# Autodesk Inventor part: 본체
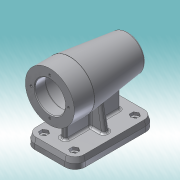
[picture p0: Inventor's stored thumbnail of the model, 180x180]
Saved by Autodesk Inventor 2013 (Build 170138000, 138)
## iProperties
Created: 2017-01
Part Number: 본체
Material: 알루미늄 6061
Document SubType Name: Modeling
Designer: dgall
Density: 2.71 g/cm^3
Mass: 795.03 g
Surface Area: 661.674 cm^2
Volume: 293.369 cm^3
Author: dgall
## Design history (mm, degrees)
sketch "스케치3"
  geometry: L1 (56, 0)-(56, 34); L2 (56, 34)-(28, 34); L3 (28, 34)-(-52.27, 24.144); L4 (-56, 0)-(56, 0); A1 r 80 centre (24, 0) between (-52.27, 24.144) and (-56, 0); 2 further points
  constraints: 8 end point, 2 point on circle, 1 centre point, 1 midpoint, 1 parallel, 1 perpendicular, 1 point on line, 1 vertical, 1 vertical alignment
  dimensions: "d4" = 68 diameter of L2 L4; "d6" = 28 distance from line of L2.end L1; "d7" = 112 dimension on A1 L1; "d8" = 80 radius of A1; "d9" = 7 deg angle of L3 L2; "d10" = 56 distance from line of point (0, 0) L1
revolve "회전1" sketch "스케치3" stored, may be unused: angle "d11" = 90 deg
sketch "스케치4"
  geometry: L1 (-50, 0)-(-50, 10.5); L2 (-50, 10.5)-(-47, 10.5); L3 (-47, 10.5)-(-47, 16); L4 (-47, 16)-(-43, 16); L5 (-43, 16)-(-43, 17.5); L6 (-43, 17.5)-(-25, 17.5); L7 (-25, 17.5)-(-25, 21); L8 (-25, 21)-(-13, 21); L9 (-13, 21)-(-13, 24); L10 (-13, 24)-(41, 24); L11 (41, 24)-(41, 21); L12 (41, 21)-(56, 21); L13 (56, 21)-(56, 0); L14 (56, 0)-(-50, 0); L15 (56, -34)-(56, 34) reference; 2 further points
  constraints: 28 end point, 12 parallel, 2 point on line, 1 midpoint, 1 perpendicular, 1 vertical
  dimensions: "d12" = 15 distance between parallel lines of L13 L11; "d14" = 54 distance between parallel lines of L11 L9; "d15" = 12 distance between parallel lines of L9 L7; "d16" = 18 distance between parallel lines of L7 L5; "d17" = 4 distance between parallel lines of L5 L3; "d18" = 3 distance between parallel lines of L3 L1; "d19" = 21 diameter of L2 L14; "d20" = 32 diameter of L4 L14; "d21" = 35 diameter of L6 L14; "d22" = 42 diameter of L8 L14; "d23" = 48 diameter of L10 L14; "d24" = 42 diameter of L12 L14
revolve "회전2" sketch "스케치4" stored, may be unused: angle "d25" = 90 deg
node "작업 평면2"
  node "작업 평면1"
sketch "스케치9"
  geometry: L1 (-21, -56)-(21, -56); L2 (35, -42)-(35, 42); L3 (21, 56)-(-21, 56); L4 (-35, 42)-(-35, -42); L5 (-35, -56)-(35, 56); L6 (35, -56)-(-35, 56); A1 r 14 centre (-21, 42) between (-21, 56) and (-35, 42); A2 r 14 centre (21, 42) between (35, 42) and (21, 56); A3 r 14 centre (21, -42) between (21, -56) and (35, -42); A4 r 14 centre (-21, -42) between (-35, -42) and (-21, -56); 1 further point
  constraints: 12 end point, 8 point on circle, 8 point on line, 8 tangent, 4 centre point, 2 equal radius, 2 midpoint, 2 parallel, 1 horizontal, 1 perpendicular
  dimensions: "d136" = 70 distance of L5.end L6.end; "d137" = 112 distance of L6.start L5.end; "d138" = 14 radius of A1; "d139" = 14 radius of A2
extrude "돌출5" join sketch "스케치9" distance "d64" = 7; taper "d65" = -15 deg
sketch "스케치10"
  geometry: L1 (-21, 56)-(21, 56); L2 (35, 42)-(35, -42); L3 (21, -56)-(-21, -56); L4 (-35, -42)-(-35, 42); A1 r 14 centre (-21, 42) between (-21, 56) and (-35, 42); A2 r 14 centre (21, 42) between (35, 42) and (21, 56); A3 r 14 centre (21, -42) between (21, -56) and (35, -42); A4 r 14 centre (-21, -42) between (-35, -42) and (-21, -56); 5 further points
  constraints: 8 end point, 8 point on circle, 8 point on line, 8 tangent, 4 centre point, 3 equal radius, 2 parallel, 1 horizontal, 1 perpendicular
  dimensions: "d67" = 70 distance of point (-35, 56) point (35, 56); "d69" = 112 distance of point (-35, -56) point (-35, 56); "d70" = 35 distance from line of L4 point (0, 0); "d71" = 56 distance from line of L3 point (0, 0); "d140" = 14 radius of A1
extrude "돌출6" join sketch "스케치10" distance "d72" = 7; taper "d73" = 0 deg
sketch "스케치12"
  geometry: 2 further points
  dimensions: "d96" = 21 horizontal distance of point (21, -41) point (0, 0); "d97" = 41 vertical distance of point (21, -41) point (0, 0)
sketch "스케치7"
  geometry: C1 r 21 at (0, 0) reference; 1 further point
  constraints: 1 vertical alignment
  dimensions: "d45" = 26 distance of point (0, 26) C1.centre
hole "구멍1" sketch "스케치7" at (0, 26) diameter "d46" = 3.242; stored, may be unused: countersink angle "d50" = 90 deg, drill point angle "d52" = 118 deg; dims "d47" = 8, "d48" = 4, "d49" = 2, "d51" = 11
sketch "스케치11"
  geometry: L1 (-4, 38)-(4, 38); L2 (4, 38)-(4, -38); L3 (4, -38)-(-4, -38); L4 (-4, -38)-(-4, 38); L5 (-23, 4)-(23, 4); L6 (23, 4)-(23, -4); L7 (23, -4)-(-23, -4); L8 (-23, -4)-(-23, 4); L9 (-21, 56)-(21, 56) reference; L10 (-35, -42)-(-35, 42) reference; L11 (21, -56)-(-21, -56) reference; L12 (35, 42)-(35, -42) reference; 1 further point
  constraints: 16 end point, 4 parallel, 2 horizontal, 2 perpendicular
  dimensions: "d74" = 8 distance between parallel lines of L7 L5; "d76" = 8 distance between parallel lines of L2 L4; "d81" = 4 distance from line of L5 point (0, 0); "d82" = 4 distance from line of L2 point (0, 0); "d141" = 18 distance between parallel lines of L1 L9; "d142" = 18 distance between parallel lines of L11 L3; "d143" = 12 distance between parallel lines of L6 L12; "d144" = 12 distance between parallel lines of L10 L8
extrude "돌출7" join sketch "스케치11" stored distance "d83" = 7; taper "d84" = 0 deg
feature "면 기울기4" dims angle "d85" = 10 deg
fillet "모깎기3" dims "d88" = 0.3
fillet "모깎기4" dims "d89" = 3
chamfer "모따기1" distance "d90" = 1; stored, may be unused: second distance "d91" = 2, angle "d92" = 45 deg
fillet "모깎기5" dims "d93" = 3
hole "구멍2" sketch "스케치12" diameter "d98" = 5; stored, may be unused: countersink angle "d102" = 90 deg, drill point angle "d104" = 0 deg; dims "d99" = 8, "d100" = 10, "d101" = 4, "d103" = 14
sketch "스케치13"
  geometry: L1 (21, -35.226)-(26, -38.113); L2 (26, -38.113)-(26, -43.887); L3 (26, -43.887)-(21, -46.774); L4 (21, -46.774)-(16, -43.887); L5 (16, -43.887)-(16, -38.113); L6 (16, -38.113)-(21, -35.226); 4 further points
  constraints: 12 end point, 1 coincident, 1 midpoint, 1 vertical alignment, 15 other
extrude "돌출8" cut sketch "스케치13" distance "d105" = 4; taper "d106" = 0 deg
fillet "모깎기8" dims "d113" = 3
sketch "스케치14"
  geometry: L1 (0, 84)-(0, 0) reference; L2 (0, 98)-(-7, 98) reference; 2 further points
  constraints: 1 other
  dimensions: "d151" = 56 distance from line of L2 point (-4, 42); "d152" = 4 distance from line of point (-4, 42) L1
feature "엠보싱1" sketch "스케치14" dims "d116" = 0.5, "d117" = 0
fillet "모깎기9" dims "d118" = 3
fillet "모깎기10" dims "d119" = 3
fillet "모깎기12" dims "d121" = 3
node "솔리드2"
pattern_circular "원형 패턴1" dims angle "d54" = 360 deg
pattern_linear "직사각형 패턴2" dims "d147" = 84, "d150" = 42
other parameters: "d26" = 74, "d59" = -7
